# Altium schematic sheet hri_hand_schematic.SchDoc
size A4
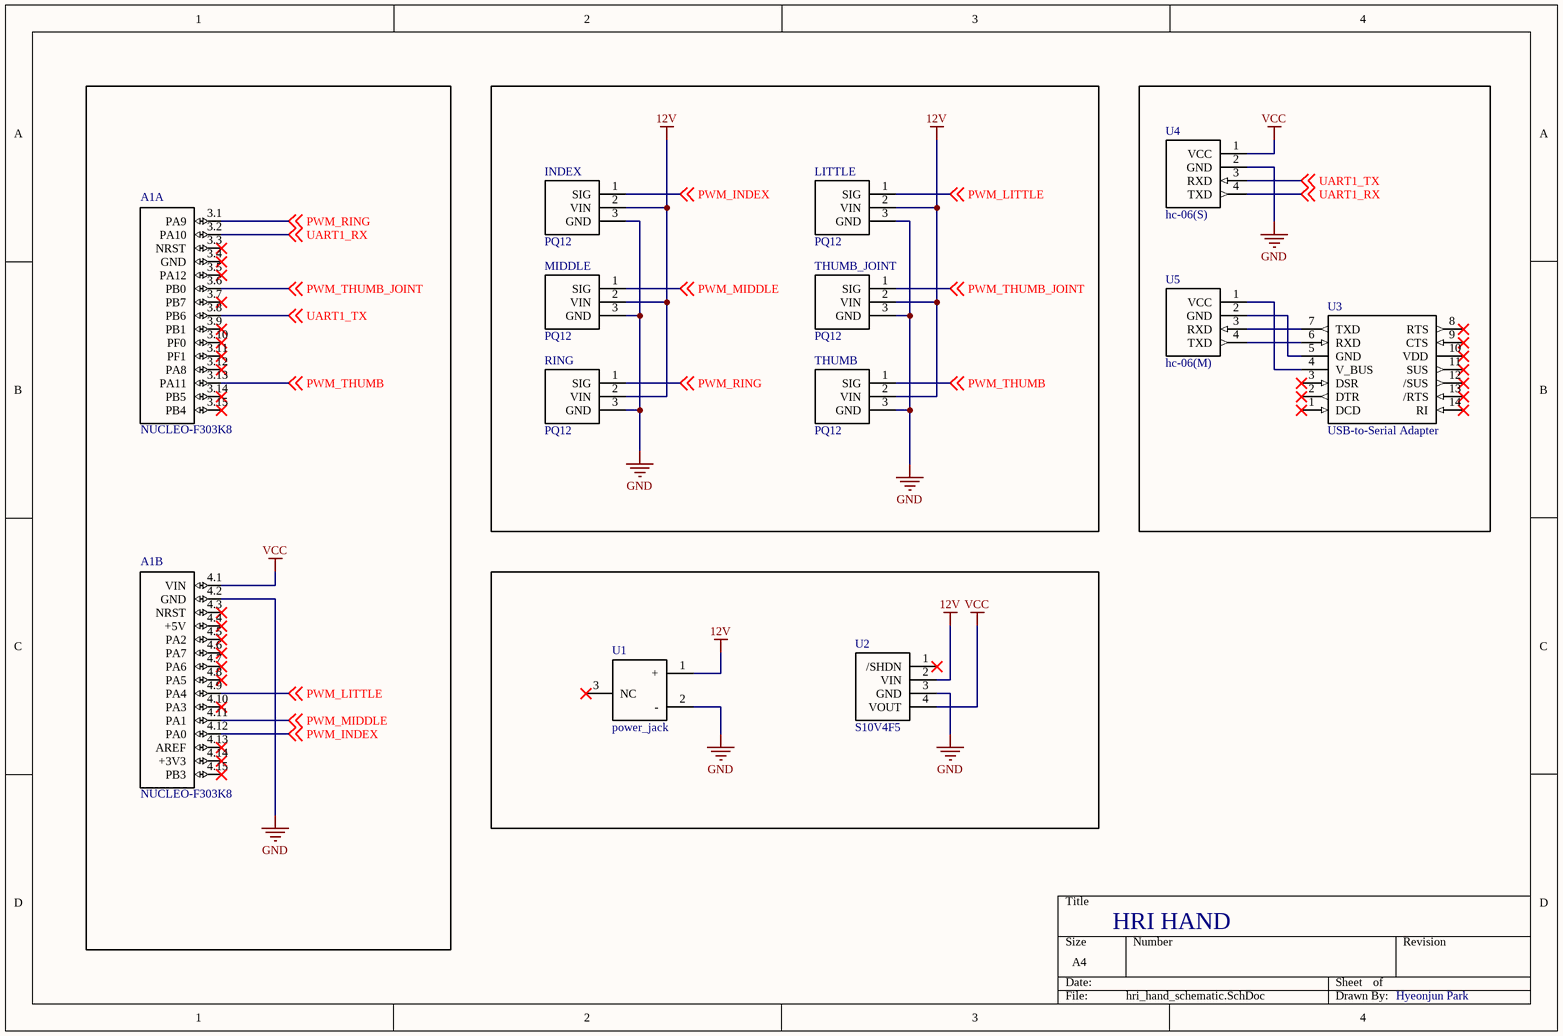
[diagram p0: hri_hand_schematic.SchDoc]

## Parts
A1  NUCLEO-F303K8  [*MODULE_NUCLEO-F303K8_NUCLEO-F303K8(Primary)]  (parts A,B of 2)
INDEX  PQ12
LITTLE  PQ12
MIDDLE  PQ12
RING  PQ12
THUMB  PQ12
THUMB_JOINT  PQ12
U1  power_jack
U2  S10V4F5
U3  USB-to-Serial Adapter
U4  hc-06(S)
U5  hc-06(M)

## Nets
12V: INDEX.2(VIN) LITTLE.2(VIN) MIDDLE.2(VIN) RING.2(VIN) THUMB.2(VIN) THUMB_JOINT.2(VIN) U1.1(+) U2.2(VIN)
GND: A1.4.2(GND) INDEX.3(GND) LITTLE.3(GND) MIDDLE.3(GND) RING.3(GND) THUMB.3(GND) THUMB_JOINT.3(GND) U1.2(-) U2.3(GND) U4.2(GND)
VCC: A1.4.1(VIN) U2.4(VOUT) U4.1(VCC)
PWM_INDEX: A1.4.12(PA0) INDEX.1(SIG) ; off-sheet PWM_INDEX
PWM_LITTLE: A1.4.9(PA4) LITTLE.1(SIG) ; off-sheet PWM_LITTLE
PWM_MIDDLE: A1.4.11(PA1) MIDDLE.1(SIG) ; off-sheet PWM_MIDDLE
PWM_RING: A1.3.1(PA9) RING.1(SIG) ; off-sheet PWM_RING
PWM_THUMB: A1.3.13(PA11) THUMB.1(SIG) ; off-sheet PWM_THUMB
PWM_THUMB_JOINT: A1.3.6(PB0) THUMB_JOINT.1(SIG) ; off-sheet PWM_THUMB_JOINT
UART1_RX: A1.3.2(PA10) U4.4(TXD) ; off-sheet UART1_RX
UART1_TX: A1.3.8(PB6) U4.3(RXD) ; off-sheet UART1_TX
NetU3_4: U3.4(V_BUS) U5.1(VCC)
NetU3_5: U3.5(GND) U5.2(GND)
NetU3_6: U3.6(RXD) U5.4(TXD)
NetU3_7: U3.7(TXD) U5.3(RXD)

Not connected (* = marked no-connect by the designer): A1 3.3(NRST)* 3.4(GND)* 3.5(PA12)* 3.7(PB7)* 3.9(PB1)* 3.10(PF0)* 3.11(PF1)* 3.12(PA8)* 3.14(PB5)* 3.15(PB4)* 4.3(NRST)* 4.4(+5V)* 4.5(PA2)* 4.6(PA7)* 4.7(PA6)* 4.8(PA5)* 4.10(PA3)* 4.13(AREF)* 4.14(+3V3)* 4.15(PB3)*; U1 3(NC)*; U2 1(/SHDN)*; U3 1(DCD)* 2(DTR)* 3(DSR)* 8(RTS)* 9(CTS)* 10(VDD)* 11(SUS)* 12(/SUS)* 13(/RTS)* 14(RI)*

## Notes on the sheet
- HRI HAND
- Hyeonjun Park

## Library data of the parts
A1 = NUCLEO-F303K8: STM32 Nucleo-32 development board with STM32F303K8T6 MCU, supports Arduino connectivity; MF: STMicroelectronics
U4 U5 = hc-06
